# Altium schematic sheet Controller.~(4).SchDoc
size A
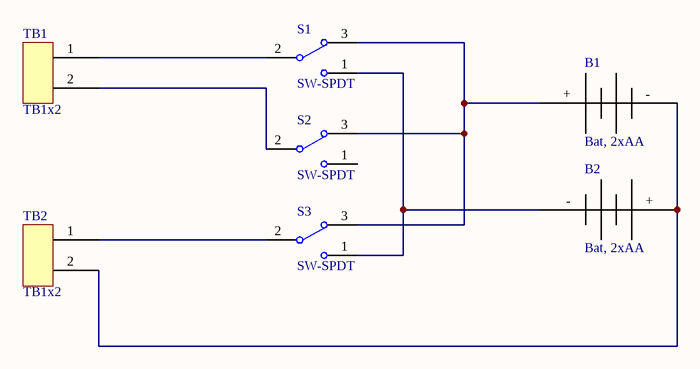
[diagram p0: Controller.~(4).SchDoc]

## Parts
B1  Bat, 2xAA  [Bat1]
B2  Bat, 2xAA  [Bat1]
S1  SW-SPDT  [Switch, SPDT, Solder Lug]
S2  SW-SPDT  [Switch, SPDT, Solder Lug]
S3  SW-SPDT  [Switch, SPDT, Solder Lug]
TB1  TB1x2
TB2  TB1x2

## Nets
NetB1_+: B1.+ S1.3 S2.3 S3.3
NetB1_-: B1.- B2.+ TB2.2
NetB2_-: B2.- S1.1 S3.1
NetS1_2: S1.2 TB1.1
NetS2_2: S2.2 TB1.2
NetS3_2: S3.2 TB2.1

Not connected (* = marked no-connect by the designer): S2 1

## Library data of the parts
S1-S3 = SW-SPDT: SPDT Subminiature Toggle Switch, Right Angle Mounting, Vertical Actuation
